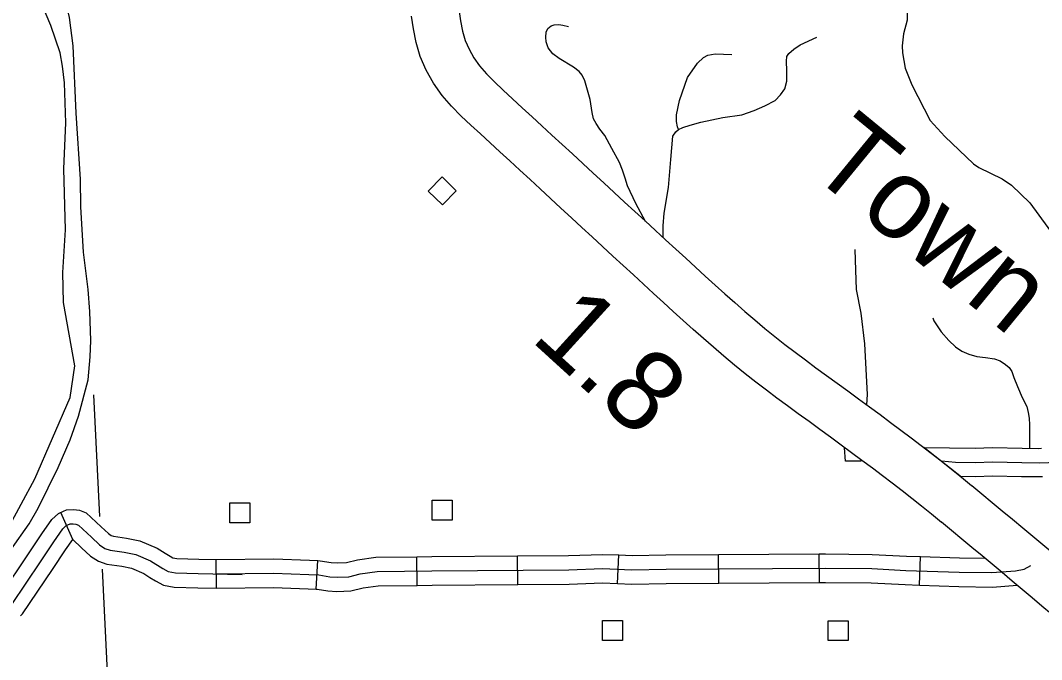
# Model space of a CAD drawing. Extents: x 1370130 to 1380143, y 377636 to 380256.
# Drawn here: x 1377248.1 to 1377398.1, y 379033.5 to 379127.4 of the extents above; entities that cross this region are included whole.
import ezdxf

# ---------------------------------------------------------------- set-up
doc = ezdxf.new("R2010")
doc.units = 0
for name, color, linetype in [('Level 15', 7, 'Continuous'), ('Level 31', 7, 'Continuous'), ('Level 32', 7, 'Continuous'), ('Level 34', 7, 'Continuous'), ('Level 35', 7, 'Continuous'), ('Level 45', 7, 'Continuous'), ('Level 48', 7, 'Continuous'), ('Level 5', 7, 'Continuous'), ('Level 56', 7, 'Continuous'), ('Level 6', 7, 'Continuous')]:
    doc.layers.add(name, color=color, linetype=linetype)

msp = doc.modelspace()

# ---------------------------------------------------------------- linework, layer by layer
at = {"layer": 'Level 15'}
for points in [[(1377312.51, 379129.09), (1377312.76, 379127.39), (1377313.05, 379125.88), (1377313.46, 379124.51), (1377314.02, 379123.2), (1377314.72, 379121.94), (1377315.56, 379120.75), (1377316.57, 379119.59), (1377317.75, 379118.41), (1377319.06, 379117.17), (1377320.43, 379115.9), (1377321.85, 379114.6), (1377323.29, 379113.28), (1377324.74, 379111.94), (1377326.21, 379110.59), (1377327.72, 379109.21), (1377329.23, 379107.82), (1377330.75, 379106.41), (1377332.27, 379105), (1377333.81, 379103.59), (1377335.34, 379102.17), (1377336.87, 379100.75), (1377338.38, 379099.35), (1377339.89, 379097.97), (1377341.4, 379096.59), (1377342.91, 379095.2), (1377344.39, 379093.83), (1377345.85, 379092.49), (1377347.3, 379091.16), (1377348.73, 379089.85), (1377350.17, 379088.55), (1377351.62, 379087.26), (1377353.07, 379085.97), (1377354.54, 379084.69), (1377356.01, 379083.42), (1377357.47, 379082.19), (1377358.93, 379081), (1377360.42, 379079.84), (1377361.94, 379078.69), (1377363.46, 379077.54), (1377364.98, 379076.41), (1377366.52, 379075.28), (1377368.09, 379074.14), (1377369.68, 379072.99), (1377371.26, 379071.83), (1377372.84, 379070.67), (1377374.4, 379069.51), (1377375.93, 379068.37), (1377377.45, 379067.24), (1377378.96, 379066.12), (1377380.46, 379064.99), (1377381.94, 379063.85), (1377383.4, 379062.7), (1377384.89, 379061.52), (1377386.38, 379060.31), (1377387.86, 379059.1)], [(1377383.45, 379053.67), (1377381.96, 379054.88), (1377380.51, 379056.06), (1377379.07, 379057.2), (1377377.64, 379058.32), (1377376.21, 379059.42), (1377374.76, 379060.52), (1377373.28, 379061.62), (1377371.75, 379062.75), (1377370.22, 379063.9), (1377368.68, 379065.04), (1377367.13, 379066.19), (1377365.56, 379067.33), (1377363.98, 379068.48), (1377362.4, 379069.62), (1377360.82, 379070.78), (1377359.26, 379071.94), (1377357.71, 379073.11), (1377356.15, 379074.29), (1377354.57, 379075.52), (1377353, 379076.8), (1377351.46, 379078.1), (1377349.95, 379079.41), (1377348.45, 379080.72), (1377346.97, 379082.03), (1377345.49, 379083.35), (1377344.03, 379084.67), (1377342.58, 379086), (1377341.12, 379087.33), (1377339.64, 379088.69), (1377338.17, 379090.05), (1377336.68, 379091.42), (1377335.16, 379092.8), (1377333.63, 379094.21), (1377332.11, 379095.62), (1377330.59, 379097.03), (1377329.07, 379098.44), (1377327.53, 379099.85), (1377325.99, 379101.27), (1377324.48, 379102.68), (1377322.98, 379104.06), (1377321.48, 379105.43), (1377320.01, 379106.79), (1377318.56, 379108.12), (1377317.11, 379109.44), (1377315.69, 379110.75), (1377314.28, 379112.05), (1377312.87, 379113.39), (1377311.44, 379114.82), (1377310.05, 379116.42), (1377308.79, 379118.2), (1377307.72, 379120.11), (1377306.86, 379122.13), (1377306.25, 379124.21), (1377305.85, 379126.22), (1377305.59, 379128.07)], [(1377387.89, 379059.09), (1377389.38, 379057.86), (1377390.87, 379056.62), (1377392.37, 379055.38), (1377393.86, 379054.14), (1377395.36, 379052.9), (1377396.85, 379051.66), (1377398.32, 379050.41), (1377399.78, 379049.18), (1377401.24, 379047.96), (1377402.69, 379046.74), (1377404.14, 379045.52), (1377405.55, 379044.29), (1377406.9, 379043.1), (1377408.23, 379041.91), (1377409.6, 379040.66), (1377410.95, 379039.27), (1377412.11, 379037.89), (1377413.21, 379036.58), (1377414.28, 379035.25), (1377415.33, 379033.92), (1377416.34, 379032.57)], [(1377406.74, 379033.39), (1377405.75, 379034.57), (1377404.72, 379035.63), (1377403.54, 379036.72), (1377402.26, 379037.86), (1377400.93, 379039.03), (1377399.58, 379040.21), (1377398.19, 379041.38), (1377396.74, 379042.59), (1377395.27, 379043.82), (1377393.81, 379045.06), (1377392.35, 379046.29), (1377390.88, 379047.52), (1377389.39, 379048.75), (1377387.9, 379049.99), (1377386.4, 379051.23), (1377384.92, 379052.46), (1377383.43, 379053.69)]]:
    msp.add_lwpolyline(points, dxfattribs=at)
at = {"layer": 'Level 31'}
msp.add_line((1377386.24, 379060.42), (1377386.38, 379060.31), dxfattribs=at)
for points in [[(1377386.38, 379060.31), (1377380.84, 379064.7), (1377388.39, 379064.59), (1377390.92, 379064.67), (1377395.28, 379064.59), (1377397.75, 379064.55), (1377398.14, 379064.57)], [(1377383.43, 379062.74), (1377385.49, 379062.53), (1377388.41, 379062.49), (1377390.94, 379062.57), (1377395.24, 379062.49), (1377397.77, 379062.45), (1377399.15, 379062.49), (1377400.96, 379062.77), (1377401.46, 379062.84)], [(1377398.26, 379060.37), (1377397.78, 379060.35), (1377395.2, 379060.39), (1377390.95, 379060.47), (1377388.43, 379060.39), (1377386.24, 379060.42)]]:
    msp.add_lwpolyline(points, dxfattribs=at)
at = {"layer": 'Level 32'}
for p, q in [((1377276.93, 379044.02), (1377276.88, 379048.22)), ((1377291.56, 379043.86), (1377291.81, 379048.06)), ((1377306.39, 379044.42), (1377306.34, 379048.62)), ((1377321.17, 379044.55), (1377321.13, 379048.75)), ((1377335.85, 379044.69), (1377336.01, 379048.89)), ((1377350.72, 379044.75), (1377350.69, 379048.95)), ((1377365.51, 379044.86), (1377365.48, 379049.06)), ((1377380.2, 379044.46), (1377380.34, 379048.66))]:
    msp.add_line(p, q, dxfattribs=at)
for points in [[(1377276.88, 379048.22), (1377285.33, 379048.3), (1377290.59, 379048.13), (1377291.81, 379048.06)], [(1377291.81, 379048.06), (1377292.16, 379048.04), (1377293.79, 379047.78), (1377294.68, 379047.71), (1377296.04, 379047.78), (1377297.65, 379048.18), (1377300.35, 379048.55), (1377306.34, 379048.62)], [(1377306.34, 379048.62), (1377308.55, 379048.64), (1377321.13, 379048.75)], [(1377321.13, 379048.75), (1377328.65, 379048.81), (1377333.63, 379048.98), (1377336.01, 379048.89)], [(1377336.01, 379048.89), (1377337.98, 379048.81), (1377342.94, 379048.89), (1377350.69, 379048.95)], [(1377350.69, 379048.95), (1377365.48, 379049.06)], [(1377365.48, 379049.06), (1377366.4, 379049.06), (1377373.25, 379048.98), (1377378.29, 379048.72), (1377380.34, 379048.66)], [(1377380.34, 379048.66), (1377386.06, 379048.47), (1377389.81, 379048.4)], [(1377276.9, 379046.12), (1377285.31, 379046.2), (1377290.49, 379046.03), (1377291.93, 379045.95), (1377293.55, 379045.69), (1377294.65, 379045.61), (1377296.35, 379045.69), (1377298.05, 379046.12), (1377300.51, 379046.46), (1377308.57, 379046.54), (1377328.7, 379046.71), (1377333.62, 379046.88), (1377337.95, 379046.71), (1377342.96, 379046.79), (1377366.4, 379046.96), (1377373.19, 379046.88), (1377378.2, 379046.62), (1377386.01, 379046.37), (1377390.85, 379046.29), (1377394.33, 379046.54), (1377395.6, 379046.79), (1377396.55, 379047.32)], [(1377276.93, 379044.02), (1377285.29, 379044.1), (1377290.39, 379043.93), (1377291.56, 379043.86)], [(1377291.56, 379043.86), (1377291.71, 379043.86), (1377293.3, 379043.6), (1377294.62, 379043.5), (1377296.66, 379043.6), (1377298.45, 379044.05), (1377300.66, 379044.36), (1377306.39, 379044.42)], [(1377306.39, 379044.42), (1377308.59, 379044.44), (1377321.17, 379044.55)], [(1377321.17, 379044.55), (1377328.74, 379044.61), (1377333.62, 379044.78), (1377335.85, 379044.69)], [(1377335.85, 379044.69), (1377337.93, 379044.61), (1377342.99, 379044.7), (1377350.72, 379044.75)], [(1377350.72, 379044.75), (1377365.51, 379044.86)], [(1377365.51, 379044.86), (1377366.39, 379044.86), (1377373.12, 379044.78), (1377378.11, 379044.53), (1377380.2, 379044.46)], [(1377380.2, 379044.46), (1377385.96, 379044.27), (1377390.91, 379044.18), (1377394.53, 379044.45)]]:
    msp.add_lwpolyline(points, dxfattribs=at)
at = {"layer": 'Level 34'}
for points in [[(1377339.96, 379097.89), (1377338.55, 379100.56), (1377337.31, 379103.13), (1377336.95, 379104.26), (1377336.59, 379105.44), (1377336.13, 379106.57), (1377335, 379108.63), (1377333.98, 379110.53), (1377333.26, 379111.45), (1377332.69, 379112.27), (1377332.33, 379112.99), (1377332.13, 379113.92), (1377331.82, 379115.82), (1377331.05, 379118.54), (1377330.64, 379119.41), (1377330.18, 379119.93), (1377329.36, 379120.59), (1377327.25, 379121.83), (1377326.33, 379122.55), (1377325.66, 379123.42), (1377325.35, 379124.29), (1377325.3, 379124.96), (1377325.35, 379125.73), (1377325.61, 379126.24), (1377326.07, 379126.66), (1377326.53, 379126.81), (1377327.2, 379126.86), (1377327.82, 379126.76), (1377328.64, 379126.55)], [(1377342.55, 379095.6), (1377342.55, 379097.27), (1377342.7, 379099.12), (1377343.32, 379102.87), (1377343.68, 379106.98), (1377343.94, 379110.42), (1377344.4, 379111.09), (1377344.81, 379111.4), (1377345.43, 379111.71), (1377346.5, 379112.07), (1377348.1, 379112.48), (1377351.33, 379113.15), (1377354.1, 379113.56), (1377355.9, 379114.22), (1377357.49, 379114.89), (1377358.98, 379115.66), (1377359.8, 379116.48), (1377360.42, 379117.41), (1377360.72, 379118.49), (1377360.72, 379120.03), (1377360.67, 379121.47), (1377360.72, 379122.14), (1377361.03, 379122.6), (1377361.75, 379123.21), (1377362.68, 379123.83), (1377365.14, 379124.96)], [(1377344.81, 379111.4), (1377344.66, 379111.81), (1377344.5, 379112.58), (1377344.5, 379113.56), (1377344.96, 379115.66), (1377346.14, 379119.05), (1377347.58, 379121.16), (1377348.45, 379121.98), (1377349.12, 379122.34), (1377350.2, 379122.55), (1377352.61, 379122.44)], [(1377372.48, 379070.94), (1377372.56, 379072.47), (1377372.19, 379079.93), (1377371.61, 379084.4), (1377370.94, 379087.88), (1377370.86, 379090.76), (1377370.76, 379093.78)], [(1377382.16, 379083.72), (1377382.32, 379083.27), (1377383.38, 379081.66), (1377384.5, 379080.4), (1377385.47, 379079.45), (1377386.42, 379078.86), (1377387.43, 379078.39), (1377388.64, 379078.06), (1377389.92, 379077.89), (1377391.22, 379077.7), (1377392.03, 379077.42), (1377392.86, 379076.9), (1377393.4, 379076.42), (1377393.78, 379075.83), (1377394.06, 379074.98), (1377394.61, 379073.63), (1377395.29, 379072.04), (1377395.96, 379070.71), (1377396.19, 379069.84), (1377396.31, 379069.01), (1377396.34, 379067.99), (1377396.34, 379064.58)]]:
    msp.add_lwpolyline(points, dxfattribs=at)
at = {"layer": 'Level 35'}
for points in [[(1377243.98, 379045.82), (1377249.38, 379053.46), (1377250.74, 379055.79), (1377253.68, 379061.74), (1377255.43, 379065.79), (1377256.65, 379069.3), (1377258.08, 379074.6), (1377258.38, 379077.98), (1377258.47, 379080.39), (1377258.3, 379084.65), (1377258.07, 379087.88), (1377257.36, 379093.36), (1377257, 379100.03), (1377256.92, 379104.1), (1377256.3, 379113.8), (1377255.85, 379123.69), (1377255.31, 379127.86), (1377253.68, 379134.93), (1377252.24, 379142.14), (1377251.33, 379145.6), (1377247.93, 379160.68)], [(1377246.23, 379052.61), (1377250.23, 379060.1), (1377255.44, 379072.05), (1377256.1, 379076.67), (1377254.45, 379086), (1377254.34, 379090.38), (1377254.74, 379096.65), (1377254.5, 379105.65), (1377254.76, 379112.39), (1377254.58, 379118.28), (1377254.31, 379120.74), (1377253.96, 379122.67), (1377252.59, 379126.68), (1377250.52, 379131.61), (1377249.59, 379134.42), (1377249.11, 379137.3), (1377248.1, 379145.33)], [(1377378.37, 379128.9), (1377378.37, 379127.5), (1377377.85, 379125.47), (1377377.64, 379123.69), (1377377.69, 379122.69), (1377378.1, 379120.42), (1377379.07, 379117.97), (1377381.76, 379112.75), (1377383.92, 379110.36), (1377388.16, 379106.38), (1377388.9, 379105.83), (1377392.33, 379104.14), (1377393.7, 379103.24), (1377396.42, 379100.63), (1377402.09, 379092.84), (1377405.07, 379088.35), (1377409.75, 379080.65), (1377411.22, 379077.37), (1377412.22, 379075.62), (1377414.67, 379072.47), (1377416.59, 379070.41), (1377418.74, 379068.55), (1377420.95, 379067.3), (1377421.19, 379067.21)]]:
    msp.add_lwpolyline(points, dxfattribs=at)
at = {"layer": 'Level 45'}
msp.add_line((1377255.81, 379051.18), (1377254.06, 379055.15), dxfattribs=at)
for points in [[(1377254.44, 379055.32), (1377254.88, 379055.51), (1377255.91, 379055.58), (1377256.78, 379055.48), (1377257.79, 379055.09), (1377259.99, 379053.01), (1377261.03, 379052.02), (1377261.44, 379051.76), (1377261.79, 379051.63), (1377263.72, 379051.37), (1377265.68, 379050.98), (1377268.22, 379049.87), (1377269.36, 379049.16)], [(1377245.23, 379042.99), (1377249.31, 379049.06), (1377251.27, 379052.01), (1377252.74, 379054.12), (1377253.69, 379054.99), (1377254.44, 379055.32)], [(1377246.83, 379041.62), (1377251.06, 379047.89), (1377253, 379050.83), (1377254.33, 379052.73), (1377254.85, 379053.2), (1377255.4, 379053.44), (1377255.86, 379053.48), (1377256.27, 379053.43), (1377256.64, 379053.28), (1377258.55, 379051.49), (1377259.73, 379050.37), (1377260.51, 379049.86), (1377261.3, 379049.58), (1377263.37, 379049.3), (1377265.05, 379048.96), (1377267.24, 379048.01), (1377269.03, 379046.89), (1377269.82, 379046.44), (1377270.88, 379046.27), (1377274.24, 379046.16), (1377280.68, 379046.04)], [(1377248.11, 379039.94), (1377248.44, 379040.24), (1377252.81, 379046.73), (1377254.74, 379049.65), (1377255.81, 379051.18)], [(1377255.81, 379051.18), (1377257.1, 379049.96), (1377258.42, 379048.71), (1377259.58, 379047.97), (1377260.8, 379047.53), (1377263.02, 379047.23), (1377264.42, 379046.95), (1377266.26, 379046.15), (1377267.13, 379045.6)], [(1377269.36, 379049.16), (1377270.11, 379048.69), (1377270.52, 379048.45), (1377271.08, 379048.37), (1377274.3, 379048.26), (1377276.88, 379048.22)], [(1377267.13, 379045.6), (1377267.95, 379045.09), (1377269.11, 379044.43), (1377270.68, 379044.18), (1377274.19, 379044.06), (1377276.93, 379044.02)]]:
    msp.add_lwpolyline(points, dxfattribs=at)
at = {"layer": 'Level 5'}
for points in [[(1377258.86, 379072.4), (1377259.74, 379054.52)], [(1377260.12, 379046.82), (1377261.95, 379009.43)]]:
    msp.add_lwpolyline(points, dxfattribs=at)
at = {"layer": 'Level 56'}
for points in [[(1377310.12, 379100.32), (1377308.02, 379102.34), (1377310.05, 379104.44), (1377312.15, 379102.42)], [(1377278.9, 379053.63), (1377278.9, 379056.54), (1377281.82, 379056.54), (1377281.82, 379053.63)], [(1377308.62, 379054.02), (1377308.62, 379056.93), (1377311.54, 379056.93), (1377311.54, 379054.02)], [(1377333.65, 379036.34), (1377333.65, 379039.26), (1377336.58, 379039.26), (1377336.58, 379036.34)], [(1377366.79, 379036.31), (1377366.79, 379039.23), (1377369.71, 379039.23), (1377369.71, 379036.31)]]:
    msp.add_lwpolyline(points, close=True, dxfattribs=at)
at = {"layer": 'Level 6'}
msp.add_lwpolyline([(1377371.65, 379062.68), (1377369.32, 379062.67), (1377369.2, 379064.63)], dxfattribs=at)

# ---------------------------------------------------------------- texts
at = {"layer": 'Level 35'}
msp.add_text('Town', height=11.827, rotation=320.6063, dxfattribs=at).set_placement((1377363.53, 379105.42))
at = {"layer": 'Level 48'}
msp.add_text('1.8', height=11.827, rotation=317.7001, dxfattribs=at).set_placement((1377322.88, 379080.54))

doc.saveas('drawing.dxf')
